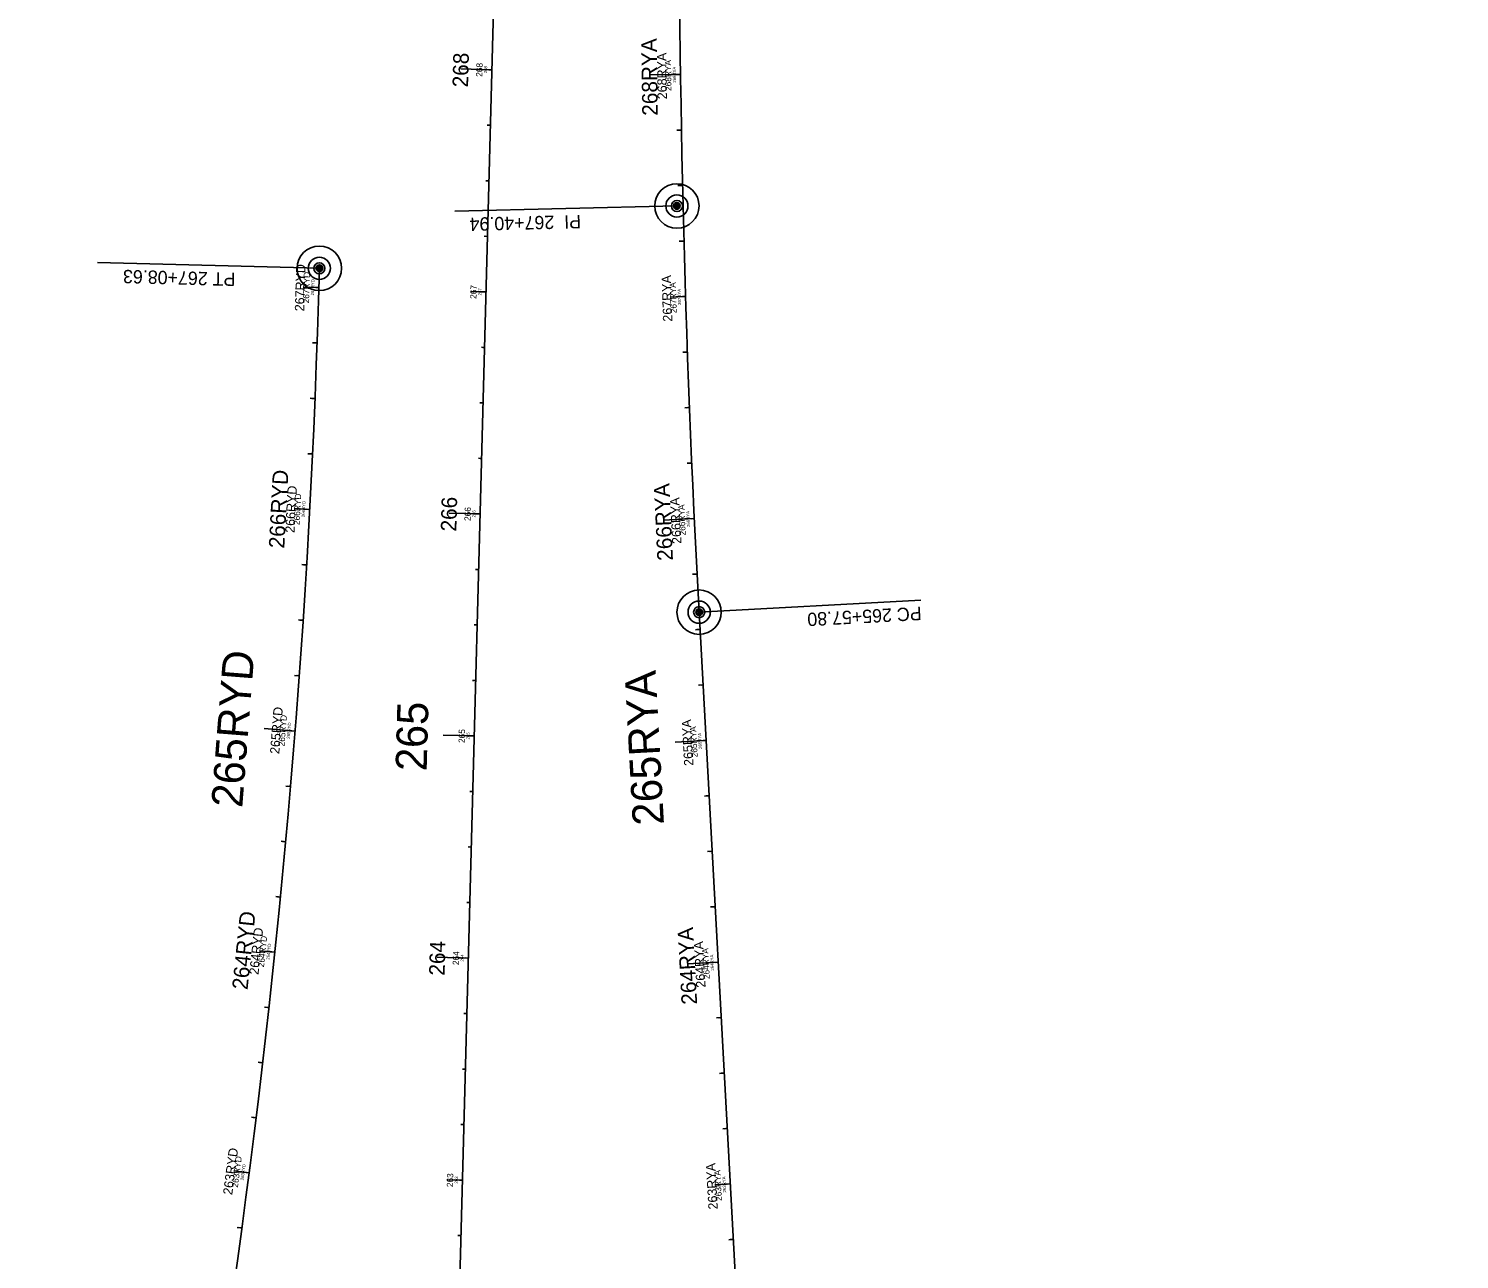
# Model space of a CAD drawing. Extents: x 564646 to 607088, y 225853 to 261760.
# Drawn here: x 598372 to 599017, y 240462 to 241016 of the extents above; entities that cross this region are included whole.
import ezdxf

# ---------------------------------------------------------------- set-up
doc = ezdxf.new("R2010")
doc.units = 0
for name, color, linetype in [('B_CONC_HIDDEN_LT', 7, 'Continuous'), ('B_CONST', 7, 'Continuous'), ('B_EXIST', 7, 'Continuous'), ('B_TEXT', 7, 'Continuous'), ('E-Easements', 7, 'Continuous'), ('E_ALI_100', 7, 'Continuous'), ('E_RW_CorporateLimits', 7, 'Continuous'), ('E_RW_EasementUtility_Text', 7, 'Continuous'), ('E_WTR_FlowLine', 7, 'Continuous'), ('EMCS_SURVEY_PT CODES', 7, 'Continuous'), ('EMCS_SURVEY_PT ELEV', 7, 'Continuous'), ('EMCS_SURVEY_PT NOTES', 7, 'Continuous'), ('Level 33', 7, 'Continuous'), ('P-Easements Floodplain', 7, 'Continuous'), ('P-Easements Temporary', 7, 'Continuous'), ('P_ALI_100_Tic', 7, 'Continuous'), ('P_ALI_20', 7, 'Continuous'), ('P_ALI_50', 7, 'Continuous'), ('P_RW_AccessPreviousProject Txt', 7, 'Continuous'), ('P_RW_EasementPerm', 7, 'Continuous'), ('P_RW_EasementTemp', 7, 'Continuous'), ('P_RW_PropertyConnector', 7, 'Continuous'), ('P_RW_Proposed', 7, 'Continuous'), ('P_WAL', 7, 'Continuous')]:
    doc.layers.add(name, color=color, linetype=linetype)

msp = doc.modelspace()

# ---------------------------------------------------------------- linework, layer by layer
at = {"layer": 'B_CONC_HIDDEN_LT'}
for p, q in [((598400.93, 234167.82), (599016.61, 257518.82)), ((598714.65, 240016.21), (598674.33, 240753.03))]:
    msp.add_line(p, q, dxfattribs=at)
for centre, radius, start, end in [((604665.36, 241080.89), 6000, 179.635818, 183.132364), ((594504.75, 241013.25), 4000, 345.22332, 358.48966)]:
    msp.add_arc(centre, radius, start, end, dxfattribs=at)
at = {"layer": 'B_CONST'}
for centre in [(598664.32, 240935.89), (598664.32, 240935.89), (598503.36, 240907.82), (598503.36, 240907.82), (598674.33, 240753.03), (598674.33, 240753.03)]:
    msp.add_circle(centre, 1.5, dxfattribs=at)
at = {"layer": 'B_EXIST'}
for centre in [(598664.32, 240935.89), (598503.36, 240907.82), (598674.33, 240753.03)]:
    msp.add_circle(centre, 5, dxfattribs=at)
at = {"layer": 'B_TEXT'}
for points in [[(598503.36, 240907.82), (598403.4, 240910.46)], [(598674.33, 240753.03), (598774.18, 240758.5)]]:
    msp.add_lwpolyline(points, dxfattribs=at)
at = {"layer": 'E-Easements'}
for centre in [(598664.32, 240935.89), (598503.36, 240907.82), (598674.33, 240753.03)]:
    msp.add_circle(centre, 2.5, dxfattribs=at)
at = {"layer": 'E_ALI_100'}
for points in [[(598578.19, 240997.26), (598580.99, 240997.18)], [(598663.18, 240995.03), (598665.98, 240995.07)], [(598578.93, 240972.23), (598580.33, 240972.19)], [(598664.99, 240970.05), (598666.39, 240970.08)], [(598578.28, 240947.24), (598579.67, 240947.2)], [(598665.5, 240945.05), (598666.9, 240945.08)], [(598577.62, 240922.25), (598579.02, 240922.21)], [(598666.12, 240920.05), (598667.52, 240920.09)], [(598500.32, 240899.28), (598503.12, 240899.2)], [(598575.56, 240897.29), (598578.36, 240897.22)], [(598665.44, 240895.01), (598668.24, 240895.1)], [(598500.93, 240874.26), (598502.33, 240874.21)], [(598576.3, 240872.26), (598577.7, 240872.23)], [(598667.67, 240870.06), (598669.07, 240870.11)], [(598499.99, 240849.28), (598501.39, 240849.23)], [(598575.64, 240847.27), (598577.04, 240847.23)], [(598668.6, 240845.08), (598670, 240845.13)], [(598498.88, 240824.32), (598500.28, 240824.25)], [(598574.98, 240822.28), (598576.38, 240822.24)], [(598669.63, 240820.09), (598671.03, 240820.15)], [(598496.23, 240799.43), (598499.02, 240799.28)], [(598572.92, 240797.33), (598575.72, 240797.25)], [(598669.37, 240795.04), (598672.17, 240795.18)], [(598496.21, 240774.41), (598497.61, 240774.32)], [(598573.66, 240772.3), (598575.06, 240772.26)], [(598672.01, 240770.14), (598673.41, 240770.21)], [(598494.64, 240749.46), (598496.04, 240749.37)], [(598573, 240747.31), (598574.4, 240747.27)], [(598673.35, 240745.17), (598674.75, 240745.24)], [(598492.91, 240724.53), (598494.31, 240724.43)], [(598572.35, 240722.31), (598573.74, 240722.28)], [(598674.72, 240720.21), (598676.12, 240720.28)], [(598489.64, 240699.72), (598492.43, 240699.5)], [(598570.29, 240697.36), (598573.09, 240697.29)], [(598674.69, 240695.17), (598677.48, 240695.32)], [(598488.99, 240674.71), (598490.39, 240674.59)], [(598571.03, 240672.33), (598572.43, 240672.3)], [(598677.45, 240670.28), (598678.85, 240670.36)], [(598486.8, 240649.81), (598488.19, 240649.68)], [(598570.37, 240647.34), (598571.77, 240647.3)], [(598678.82, 240645.32), (598680.22, 240645.39)], [(598484.45, 240624.93), (598485.84, 240624.79)], [(598569.71, 240622.35), (598571.11, 240622.31)], [(598680.19, 240620.35), (598681.58, 240620.43)], [(598480.55, 240600.21), (598483.34, 240599.92)], [(598567.65, 240597.4), (598570.45, 240597.32)], [(598680.15, 240595.32), (598682.95, 240595.47)], [(598479.28, 240575.22), (598480.68, 240575.06)], [(598568.39, 240572.37), (598569.79, 240572.33)], [(598682.92, 240570.43), (598684.32, 240570.51)], [(598476.47, 240550.38), (598477.86, 240550.22)], [(598567.73, 240547.38), (598569.13, 240547.34)], [(598684.28, 240545.47), (598685.68, 240545.54)], [(598473.5, 240525.57), (598474.89, 240525.4)], [(598567.07, 240522.38), (598568.47, 240522.35)], [(598685.65, 240520.5), (598687.05, 240520.58)], [(598468.99, 240500.95), (598471.76, 240500.59)], [(598565.02, 240497.43), (598567.81, 240497.36)], [(598685.62, 240495.47), (598688.41, 240495.62)], [(598467.09, 240476), (598468.48, 240475.81)], [(598565.76, 240472.4), (598567.16, 240472.36)], [(598688.38, 240470.58), (598689.78, 240470.66)]]:
    msp.add_lwpolyline(points, dxfattribs=at)
at = {"layer": 'E_WTR_FlowLine'}
for centre in [(598664.32, 240935.89), (598503.36, 240907.82), (598674.33, 240753.03)]:
    msp.add_circle(centre, 0.5, dxfattribs=at)
at = {"layer": 'EMCS_SURVEY_PT CODES'}
for p, q in [((598400.93, 234167.82), (599016.61, 257518.82)), ((598714.65, 240016.21), (598674.33, 240753.03))]:
    msp.add_line(p, q, dxfattribs=at)
for centre, radius, start, end in [((604665.36, 241080.89), 6000, 179.635818, 183.132364), ((594504.75, 241013.25), 4000, 345.22332, 358.48966)]:
    msp.add_arc(centre, radius, start, end, dxfattribs=at)
at = {"layer": 'EMCS_SURVEY_PT ELEV'}
for p, q in [((598400.93, 234167.82), (599016.61, 257518.82)), ((598400.93, 234167.82), (599016.61, 257518.82)), ((598714.65, 240016.21), (598674.33, 240753.03)), ((598714.65, 240016.21), (598674.33, 240753.03))]:
    msp.add_line(p, q, dxfattribs=at)
for centre, radius, start, end in [((604665.36, 241080.89), 6000, 179.635818, 183.132364), ((604665.36, 241080.89), 6000, 179.635818, 183.132364), ((594504.75, 241013.25), 4000, 345.22332, 358.48966), ((594504.75, 241013.25), 4000, 345.22332, 358.48966)]:
    msp.add_arc(centre, radius, start, end, dxfattribs=at)
at = {"layer": 'Level 33'}
for points in [[(598579.59, 240997.22), (598580.99, 240997.18)], [(598664.58, 240995.05), (598665.98, 240995.07)], [(598579.63, 240972.21), (598580.33, 240972.19)], [(598665.69, 240970.06), (598666.39, 240970.08)], [(598578.98, 240947.22), (598579.67, 240947.2)], [(598666.2, 240945.07), (598666.9, 240945.08)], [(598578.32, 240922.23), (598579.02, 240922.21)], [(598666.82, 240920.07), (598667.52, 240920.09)], [(598501.72, 240899.24), (598503.12, 240899.2)], [(598576.96, 240897.25), (598578.36, 240897.22)], [(598666.84, 240895.06), (598668.24, 240895.1)], [(598501.63, 240874.23), (598502.33, 240874.21)], [(598577, 240872.24), (598577.7, 240872.23)], [(598668.37, 240870.09), (598669.07, 240870.11)], [(598500.69, 240849.26), (598501.39, 240849.23)], [(598576.34, 240847.25), (598577.04, 240847.23)], [(598669.3, 240845.1), (598670, 240845.13)], [(598499.58, 240824.28), (598500.28, 240824.25)], [(598575.68, 240822.26), (598576.38, 240822.24)], [(598670.33, 240820.12), (598671.03, 240820.15)], [(598497.63, 240799.36), (598499.02, 240799.28)], [(598574.32, 240797.29), (598575.72, 240797.25)], [(598670.77, 240795.11), (598672.17, 240795.18)], [(598496.91, 240774.36), (598497.61, 240774.32)], [(598574.36, 240772.28), (598575.06, 240772.26)], [(598672.71, 240770.17), (598673.41, 240770.21)], [(598495.34, 240749.42), (598496.04, 240749.37)], [(598573.7, 240747.29), (598574.4, 240747.27)], [(598674.05, 240745.21), (598674.75, 240745.24)], [(598493.61, 240724.48), (598494.31, 240724.43)], [(598573.04, 240722.3), (598573.74, 240722.28)], [(598675.42, 240720.24), (598676.12, 240720.28)], [(598491.03, 240699.61), (598492.43, 240699.5)], [(598571.69, 240697.32), (598573.09, 240697.29)], [(598676.09, 240695.24), (598677.48, 240695.32)], [(598489.69, 240674.65), (598490.39, 240674.59)], [(598571.73, 240672.31), (598572.43, 240672.3)], [(598678.15, 240670.32), (598678.85, 240670.36)], [(598487.5, 240649.75), (598488.19, 240649.68)], [(598571.07, 240647.32), (598571.77, 240647.3)], [(598679.52, 240645.36), (598680.22, 240645.39)], [(598485.15, 240624.86), (598485.84, 240624.79)], [(598570.41, 240622.33), (598571.11, 240622.31)], [(598680.88, 240620.39), (598681.58, 240620.43)], [(598481.94, 240600.06), (598483.34, 240599.92)], [(598569.05, 240597.36), (598570.45, 240597.32)], [(598681.55, 240595.39), (598682.95, 240595.47)], [(598479.98, 240575.14), (598480.68, 240575.06)], [(598569.09, 240572.35), (598569.79, 240572.33)], [(598683.62, 240570.47), (598684.32, 240570.51)], [(598477.16, 240550.3), (598477.86, 240550.22)], [(598568.43, 240547.36), (598569.13, 240547.34)], [(598684.98, 240545.51), (598685.68, 240545.54)], [(598474.19, 240525.48), (598474.89, 240525.4)], [(598567.77, 240522.37), (598568.47, 240522.35)], [(598686.35, 240520.54), (598687.05, 240520.58)], [(598470.37, 240500.77), (598471.76, 240500.59)], [(598566.41, 240497.39), (598567.81, 240497.36)], [(598687.02, 240495.54), (598688.41, 240495.62)], [(598467.79, 240475.91), (598468.48, 240475.81)], [(598566.46, 240472.38), (598567.16, 240472.36)], [(598689.08, 240470.62), (598689.78, 240470.66)]]:
    msp.add_lwpolyline(points, dxfattribs=at)
at = {"layer": 'P-Easements Floodplain'}
for p, q in [((598400.93, 234167.82), (599016.61, 257518.82)), ((598714.65, 240016.21), (598674.33, 240753.03))]:
    msp.add_line(p, q, dxfattribs=at)
for centre, radius, start, end in [((604665.36, 241080.89), 6000, 179.635818, 183.132364), ((594504.75, 241013.25), 4000, 345.22332, 358.48966)]:
    msp.add_arc(centre, radius, start, end, dxfattribs=at)
at = {"layer": 'P-Easements Temporary'}
for centre in [(598664.32, 240935.89), (598503.36, 240907.82), (598674.33, 240753.03)]:
    msp.add_circle(centre, 10, dxfattribs=at)
at = {"layer": 'P_ALI_100_Tic'}
for points in [[(598567, 240997.55), (598580.99, 240997.18)], [(598651.98, 240994.87), (598665.98, 240995.07)], [(598561.73, 240797.62), (598575.72, 240797.25)], [(598658.18, 240794.51), (598672.17, 240795.18)], [(598556.45, 240597.69), (598570.45, 240597.32)], [(598668.97, 240594.7), (598682.95, 240595.47)]]:
    msp.add_lwpolyline(points, dxfattribs=at)
at = {"layer": 'P_ALI_20'}
for points in [[(598574, 240997.37), (598580.99, 240997.18)], [(598658.98, 240994.97), (598665.98, 240995.07)], [(598496.13, 240899.4), (598503.12, 240899.2)], [(598571.36, 240897.4), (598578.36, 240897.22)], [(598661.24, 240894.88), (598668.24, 240895.1)], [(598492.03, 240799.66), (598499.02, 240799.28)], [(598568.72, 240797.44), (598575.72, 240797.25)], [(598665.18, 240794.84), (598672.17, 240795.18)], [(598478.47, 240700.6), (598492.43, 240699.5)], [(598559.09, 240697.66), (598573.09, 240697.29)], [(598663.51, 240694.55), (598677.48, 240695.32)], [(598476.37, 240600.64), (598483.34, 240599.92)], [(598563.45, 240597.51), (598570.45, 240597.32)], [(598675.96, 240595.09), (598682.95, 240595.47)], [(598464.82, 240501.49), (598471.76, 240500.59)], [(598560.82, 240497.54), (598567.81, 240497.36)], [(598681.42, 240495.24), (598688.41, 240495.62)]]:
    msp.add_lwpolyline(points, dxfattribs=at)
at = {"layer": 'P_ALI_50'}
msp.add_lwpolyline([(598664.32, 240935.89), (598564.35, 240933.48)], dxfattribs=at)
at = {"layer": 'P_RW_AccessPreviousProject Txt'}
for points in [[(598661.78, 240995.01), (598665.98, 240995.07)], [(598664.29, 240970.04), (598666.39, 240970.08)], [(598664.8, 240945.03), (598666.9, 240945.08)], [(598665.42, 240920.03), (598667.52, 240920.09)], [(598498.93, 240899.32), (598503.12, 240899.2)], [(598664.04, 240894.97), (598668.24, 240895.1)], [(598500.23, 240874.28), (598502.33, 240874.21)], [(598666.97, 240870.04), (598669.07, 240870.11)], [(598499.29, 240849.31), (598501.39, 240849.23)], [(598667.9, 240845.05), (598670, 240845.13)], [(598498.18, 240824.35), (598500.28, 240824.25)], [(598668.93, 240820.06), (598671.03, 240820.15)], [(598494.83, 240799.51), (598499.02, 240799.28)], [(598667.97, 240794.98), (598672.17, 240795.18)], [(598495.51, 240774.45), (598497.61, 240774.32)], [(598671.31, 240770.1), (598673.41, 240770.21)], [(598493.94, 240749.51), (598496.04, 240749.37)], [(598672.66, 240745.13), (598674.75, 240745.24)], [(598492.21, 240724.58), (598494.31, 240724.43)], [(598674.02, 240720.17), (598676.12, 240720.28)], [(598488.24, 240699.83), (598492.43, 240699.5)], [(598673.29, 240695.09), (598677.48, 240695.32)], [(598488.3, 240674.76), (598490.39, 240674.59)], [(598676.75, 240670.24), (598678.85, 240670.36)], [(598486.1, 240649.87), (598488.19, 240649.68)], [(598678.12, 240645.28), (598680.22, 240645.39)], [(598483.75, 240625), (598485.84, 240624.79)], [(598679.49, 240620.32), (598681.58, 240620.43)], [(598479.16, 240600.35), (598483.34, 240599.92)], [(598678.76, 240595.24), (598682.95, 240595.47)], [(598478.59, 240575.29), (598480.68, 240575.06)], [(598682.22, 240570.39), (598684.32, 240570.51)], [(598475.77, 240550.46), (598477.86, 240550.22)], [(598683.58, 240545.43), (598685.68, 240545.54)], [(598472.8, 240525.65), (598474.89, 240525.4)], [(598684.95, 240520.47), (598687.05, 240520.58)], [(598467.6, 240501.13), (598471.76, 240500.59)], [(598684.22, 240495.39), (598688.41, 240495.62)], [(598466.4, 240476.09), (598468.48, 240475.81)], [(598687.68, 240470.54), (598689.78, 240470.66)]]:
    msp.add_lwpolyline(points, dxfattribs=at)
at = {"layer": 'P_RW_EasementPerm'}
for points in [[(598574, 240997.37), (598580.99, 240997.18)], [(598658.98, 240994.97), (598665.98, 240995.07)], [(598499.63, 240899.3), (598503.12, 240899.2)], [(598574.86, 240897.31), (598578.36, 240897.22)], [(598664.74, 240894.99), (598668.24, 240895.1)], [(598492.03, 240799.66), (598499.02, 240799.28)], [(598568.72, 240797.44), (598575.72, 240797.25)], [(598665.18, 240794.84), (598672.17, 240795.18)], [(598488.94, 240699.78), (598492.43, 240699.5)], [(598569.59, 240697.38), (598573.09, 240697.29)], [(598673.99, 240695.13), (598677.48, 240695.32)], [(598476.37, 240600.64), (598483.34, 240599.92)], [(598563.45, 240597.51), (598570.45, 240597.32)], [(598675.96, 240595.09), (598682.95, 240595.47)], [(598468.29, 240501.04), (598471.76, 240500.59)], [(598564.32, 240497.45), (598567.81, 240497.36)], [(598684.92, 240495.43), (598688.41, 240495.62)]]:
    msp.add_lwpolyline(points, dxfattribs=at)
at = {"layer": 'P_RW_EasementTemp'}
for p, q in [((598400.93, 234167.82), (599016.61, 257518.82)), ((598714.65, 240016.21), (598674.33, 240753.03))]:
    msp.add_line(p, q, dxfattribs=at)
for centre, radius, start, end in [((604665.36, 241080.89), 6000, 179.635818, 183.132364), ((594504.75, 241013.25), 4000, 345.22332, 358.48966)]:
    msp.add_arc(centre, radius, start, end, dxfattribs=at)
at = {"layer": 'P_RW_PropertyConnector'}
for p, q in [((598400.93, 234167.82), (599016.61, 257518.82)), ((598714.65, 240016.21), (598674.33, 240753.03))]:
    msp.add_line(p, q, dxfattribs=at)
for centre, radius, start, end in [((604665.36, 241080.89), 6000, 179.635818, 183.132364), ((594504.75, 241013.25), 4000, 345.22332, 358.48966)]:
    msp.add_arc(centre, radius, start, end, dxfattribs=at)
at = {"layer": 'P_WAL'}
for centre in [(598664.32, 240935.89), (598503.36, 240907.82), (598674.33, 240753.03)]:
    msp.add_circle(centre, 1, dxfattribs=at)

# ---------------------------------------------------------------- texts
for s, rotation, p in [('268', 88.48966, (598576.71, 240993.99)), ('268RYA', 90.81952, (598661.88, 240987.66)), ('267RYD', 88.36604, (598498.72, 240892.01)), ('267', 88.48966, (598574.07, 240894.02)), ('267RYA', 91.77445, (598664.27, 240887.62)), ('266RYD', 86.93365, (598494.44, 240792.21)), ('266', 88.48966, (598571.44, 240794.06)), ('266RYA', 92.72938, (598668.32, 240787.63)), ('265RYD', 85.50125, (598487.67, 240692.55)), ('265RYA', 93.13236, (598673.69, 240687.75)), ('265', 88.48966, (598568.8, 240694.09)), ('264RYD', 84.06886, (598478.4, 240593.08)), ('264', 88.48966, (598566.16, 240594.13)), ('264RYA', 93.13236, (598679.16, 240587.9)), ('263RYD', 82.63646, (598466.66, 240493.89)), ('263RYA', 93.13236, (598684.62, 240488.05)), ('263', 88.48966, (598563.53, 240494.16))]:
    msp.add_text(s, height=2.8, rotation=rotation).set_placement(p)
at = {"layer": 'B_TEXT'}
for s, rotation, p in [('PT 267+08.63', 178.48966, (598465.65, 240905.82)), ('PC 265+57.80', 183.13236, (598774.34, 240755.5))]:
    msp.add_text(s, height=6, rotation=rotation, dxfattribs=at).set_placement(p)
at = {"layer": 'E_RW_CorporateLimits'}
for s, rotation, p in [('265RYD', 85.50125, (598468.62, 240664.72)), ('265RYA', 93.13236, (598658.53, 240657.46)), ('265', 88.48966, (598551.66, 240681.31))]:
    msp.add_text(s, height=14, rotation=rotation, dxfattribs=at).set_placement(p)
at = {"layer": 'E_RW_EasementUtility_Text'}
for s, rotation, p in [('268', 88.48966, (598578.85, 240995.59)), ('268RYA', 90.81952, (598663.93, 240991.37)), ('267RYD', 88.36604, (598500.92, 240895.6)), ('267', 88.48966, (598576.21, 240895.62)), ('267RYA', 91.77445, (598666.25, 240891.36)), ('266RYD', 86.93365, (598496.73, 240795.75)), ('266', 88.48966, (598573.58, 240795.65)), ('266RYA', 92.72938, (598670.25, 240791.41)), ('265RYD', 85.50125, (598490.05, 240696.03)), ('265', 88.48966, (598570.94, 240695.69)), ('265RYA', 93.13236, (598675.59, 240691.53)), ('264RYD', 84.06886, (598480.87, 240596.5)), ('264', 88.48966, (598568.31, 240595.72)), ('264RYA', 93.13236, (598681.05, 240591.68)), ('263RYD', 82.63646, (598469.21, 240497.24)), ('263', 88.48966, (598565.67, 240495.76)), ('263RYA', 93.13236, (598686.52, 240491.83))]:
    msp.add_text(s, height=1.4, rotation=rotation, dxfattribs=at).set_placement(p)
at = {"layer": 'EMCS_SURVEY_PT NOTES'}
for s, rotation, p in [('268RYA', 90.81952, (598659.83, 240983.96)), ('267RYD', 88.36604, (598496.51, 240888.42)), ('267RYA', 91.77445, (598662.28, 240883.88)), ('266RYD', 86.93365, (598492.15, 240788.67)), ('266RYA', 92.72938, (598666.4, 240783.86)), ('265RYD', 85.50125, (598485.29, 240689.07)), ('265RYA', 93.13236, (598671.8, 240683.96)), ('264RYD', 84.06886, (598475.94, 240589.67)), ('264RYA', 93.13236, (598677.26, 240584.11)), ('263RYD', 82.63646, (598464.11, 240490.53)), ('263RYA', 93.13236, (598682.73, 240484.26))]:
    msp.add_text(s, height=4.2, rotation=rotation, dxfattribs=at).set_placement(p)
at = {"layer": 'P_ALI_50'}
msp.add_text('PI  267+40.94', height=6, rotation=181.38409, dxfattribs=at).set_placement((598621.09, 240931.85))
at = {"layer": 'P_RW_Proposed'}
for s, rotation, p in [('268RYA', 90.81952, (598655.74, 240976.54)), ('268', 88.48966, (598570.28, 240989.19)), ('266RYD', 86.93365, (598487.56, 240781.6)), ('266RYA', 92.72938, (598662.56, 240776.32)), ('266', 88.48966, (598565.01, 240789.26)), ('264RYD', 84.06886, (598471.01, 240582.83)), ('264RYA', 93.13236, (598673.47, 240576.54)), ('264', 88.48966, (598559.74, 240589.33))]:
    msp.add_text(s, height=7, rotation=rotation, dxfattribs=at).set_placement(p)

doc.saveas('drawing.dxf')
